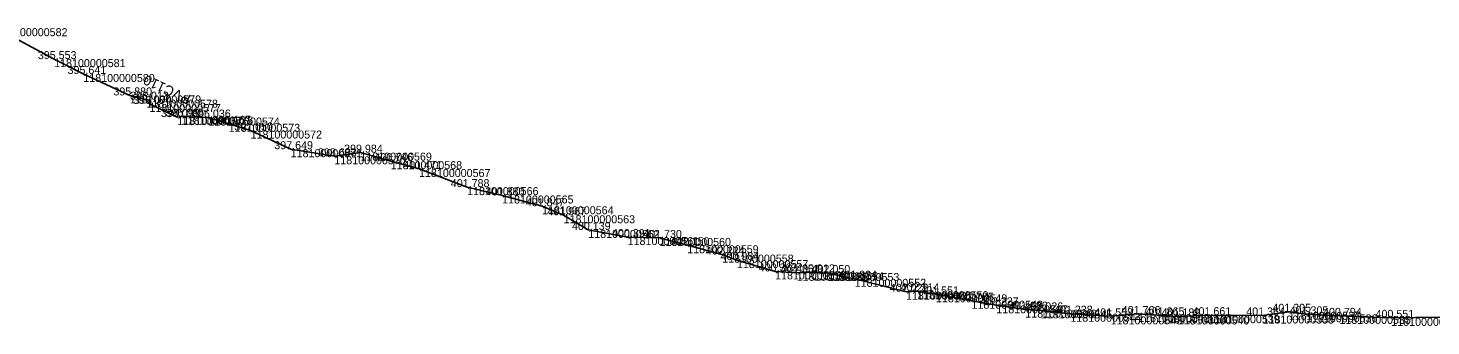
# Model space of a CAD drawing. Extents: x -727171 to -722443, y -945718 to -941834.
# Drawn here: x -723699.8 to -723489.4, y -945345 to -945300.3 of the extents above; entities that cross this region are included whole.
import ezdxf

# ---------------------------------------------------------------- set-up
doc = ezdxf.new("R2010")
doc.units = 0
for name, color, linetype in [('Vrstva 28', 7, 'Continuous'), ('Vrstva 31', 7, 'Continuous'), ('Vrstva 33', 7, 'Continuous'), ('Vrstva 35', 7, 'Continuous'), ('Vrstva 60', 7, 'Continuous'), ('Vrstva 61', 7, 'Continuous')]:
    doc.layers.add(name, color=color, linetype=linetype)

msp = doc.modelspace()

# ---------------------------------------------------------------- linework, layer by layer
at = {"layer": 'Vrstva 28'}
msp.add_lwpolyline([(-723484.45, -945343.68), (-723495.39, -945343.82), (-723503.17, -945343.52), (-723508.17, -945343.29), (-723510.76, -945342.91), (-723514.69, -945343.46), (-723522.83, -945343.42), (-723527.38, -945343.61), (-723529.76, -945343.45), (-723533.35, -945343.24), (-723537.47, -945343.59), (-723543.52, -945343.2), (-723547.95, -945342.7), (-723550.28, -945342.59), (-723554.62, -945341.94), (-723558.35, -945341.25), (-723563.68, -945340.29), (-723566.51, -945339.82), (-723568.16, -945339.9), (-723575.86, -945337.96), (-723579.88, -945337.1), (-723582.19, -945336.99), (-723584.56, -945337.06), (-723587.8, -945336.85), (-723593.53, -945335.15), (-723595.73, -945334.33), (-723600.98, -945332.93), (-723605.13, -945331.83), (-723609.91, -945331.7), (-723615.82, -945330.63), (-723619.51, -945328.43), (-723622.74, -945327.08), (-723628.74, -945325.46), (-723633.99, -945324.21), (-723641.2, -945321.48), (-723645.45, -945320.32), (-723649.99, -945319.03), (-723653.9, -945319.58), (-723660.45, -945318.52), (-723666.46, -945315.72), (-723669.74, -945314.71), (-723672.79, -945313.77), (-723676.78, -945313.62), (-723677.46, -945313.7), (-723681.63, -945311.73), (-723682.08, -945311.09), (-723684.59, -945310.45), (-723691.55, -945307.23), (-723695.92, -945305), (-723704.63, -945300.36)], dxfattribs=at)
at = {"layer": 'Vrstva 31'}
msp.add_lwpolyline([(-723484.45, -945343.68), (-723495.39, -945343.82), (-723503.17, -945343.52), (-723508.17, -945343.29), (-723510.76, -945342.91), (-723514.69, -945343.46), (-723522.83, -945343.42), (-723527.38, -945343.61), (-723529.76, -945343.45), (-723533.35, -945343.24), (-723537.47, -945343.59), (-723543.52, -945343.2), (-723547.95, -945342.7), (-723550.28, -945342.59), (-723554.62, -945341.94), (-723558.35, -945341.25), (-723563.68, -945340.29), (-723566.51, -945339.82), (-723568.16, -945339.9), (-723575.86, -945337.96), (-723579.88, -945337.1), (-723582.19, -945336.99), (-723584.56, -945337.06), (-723587.8, -945336.85), (-723593.53, -945335.15), (-723595.73, -945334.33), (-723600.98, -945332.93), (-723605.13, -945331.83), (-723609.91, -945331.7), (-723615.82, -945330.63), (-723619.51, -945328.43), (-723622.74, -945327.08), (-723628.74, -945325.46), (-723633.99, -945324.21), (-723641.2, -945321.48), (-723645.45, -945320.32), (-723649.99, -945319.03), (-723653.9, -945319.58), (-723660.45, -945318.52), (-723666.46, -945315.72), (-723669.74, -945314.71), (-723672.79, -945313.77), (-723676.78, -945313.62), (-723677.46, -945313.7), (-723681.63, -945311.73), (-723682.08, -945311.09), (-723684.59, -945310.45), (-723691.55, -945307.23), (-723695.92, -945305), (-723704.63, -945300.36)], dxfattribs=at)
at = {"layer": 'Vrstva 33'}
msp.add_lwpolyline([(-723484.45, -945343.68), (-723495.39, -945343.82), (-723503.17, -945343.52), (-723508.17, -945343.29), (-723510.76, -945342.91), (-723514.69, -945343.46), (-723522.83, -945343.42), (-723527.38, -945343.61), (-723529.76, -945343.45), (-723533.35, -945343.24), (-723537.47, -945343.59), (-723543.52, -945343.2), (-723547.95, -945342.7), (-723550.28, -945342.59), (-723554.62, -945341.94), (-723558.35, -945341.25), (-723563.68, -945340.29), (-723566.51, -945339.82), (-723568.16, -945339.9), (-723575.86, -945337.96), (-723579.88, -945337.1), (-723582.19, -945336.99), (-723584.56, -945337.06), (-723587.8, -945336.85), (-723593.53, -945335.15), (-723595.73, -945334.33), (-723600.98, -945332.93), (-723605.13, -945331.83), (-723609.91, -945331.7), (-723615.82, -945330.63), (-723619.51, -945328.43), (-723622.74, -945327.08), (-723628.74, -945325.46), (-723633.99, -945324.21), (-723641.2, -945321.48), (-723645.45, -945320.32), (-723649.99, -945319.03), (-723653.9, -945319.58), (-723660.45, -945318.52), (-723666.46, -945315.72), (-723669.74, -945314.71), (-723672.79, -945313.77), (-723676.78, -945313.62), (-723677.46, -945313.7), (-723681.63, -945311.73), (-723682.08, -945311.09), (-723684.59, -945310.45), (-723691.55, -945307.23), (-723695.92, -945305), (-723704.63, -945300.36)], dxfattribs=at)
at = {"layer": 'Vrstva 35'}
msp.add_lwpolyline([(-723676.78, -945313.62), (-723677.46, -945313.7), (-723681.63, -945311.73), (-723682.08, -945311.09)], dxfattribs=at)
at = {"layer": 'Vrstva 60'}
for p, q in [((-723695.92, -945305), (-723695.92, -945305)), ((-723691.55, -945307.23), (-723691.55, -945307.23)), ((-723684.59, -945310.45), (-723684.59, -945310.45)), ((-723682.08, -945311.09), (-723682.08, -945311.09)), ((-723681.63, -945311.73), (-723681.63, -945311.73)), ((-723677.46, -945313.7), (-723677.46, -945313.7)), ((-723676.78, -945313.62), (-723676.78, -945313.62)), ((-723672.79, -945313.77), (-723672.79, -945313.77)), ((-723669.74, -945314.71), (-723669.74, -945314.71)), ((-723666.46, -945315.72), (-723666.46, -945315.72)), ((-723660.45, -945318.52), (-723660.45, -945318.52)), ((-723653.9, -945319.58), (-723653.9, -945319.58)), ((-723649.99, -945319.03), (-723649.99, -945319.03)), ((-723645.45, -945320.32), (-723645.45, -945320.32)), ((-723641.2, -945321.48), (-723641.2, -945321.48)), ((-723633.99, -945324.21), (-723633.99, -945324.21)), ((-723628.74, -945325.46), (-723628.74, -945325.46)), ((-723622.74, -945327.08), (-723622.74, -945327.08)), ((-723619.51, -945328.43), (-723619.51, -945328.43)), ((-723615.82, -945330.63), (-723615.82, -945330.63)), ((-723609.91, -945331.7), (-723609.91, -945331.7)), ((-723605.13, -945331.83), (-723605.13, -945331.83)), ((-723600.98, -945332.93), (-723600.98, -945332.93)), ((-723595.73, -945334.33), (-723595.73, -945334.33)), ((-723593.53, -945335.15), (-723593.53, -945335.15)), ((-723587.8, -945336.85), (-723587.8, -945336.85)), ((-723582.19, -945336.99), (-723582.19, -945336.99)), ((-723584.56, -945337.06), (-723584.56, -945337.06)), ((-723579.88, -945337.1), (-723579.88, -945337.1)), ((-723575.86, -945337.96), (-723575.86, -945337.96)), ((-723568.16, -945339.9), (-723568.16, -945339.9)), ((-723566.51, -945339.82), (-723566.51, -945339.82)), ((-723563.68, -945340.29), (-723563.68, -945340.29)), ((-723558.35, -945341.25), (-723558.35, -945341.25)), ((-723554.62, -945341.94), (-723554.62, -945341.94)), ((-723550.28, -945342.59), (-723550.28, -945342.59)), ((-723547.95, -945342.7), (-723547.95, -945342.7)), ((-723543.52, -945343.2), (-723543.52, -945343.2)), ((-723533.35, -945343.24), (-723533.35, -945343.24)), ((-723510.76, -945342.91), (-723510.76, -945342.91)), ((-723508.17, -945343.29), (-723508.17, -945343.29)), ((-723537.47, -945343.59), (-723537.47, -945343.59)), ((-723529.76, -945343.45), (-723529.76, -945343.45)), ((-723527.38, -945343.61), (-723527.38, -945343.61)), ((-723522.83, -945343.42), (-723522.83, -945343.42)), ((-723514.69, -945343.46), (-723514.69, -945343.46)), ((-723503.17, -945343.52), (-723503.17, -945343.52)), ((-723495.39, -945343.82), (-723495.39, -945343.82))]:
    msp.add_line(p, q, dxfattribs=at)

# ---------------------------------------------------------------- texts
at = {"layer": 'Vrstva 35'}
msp.add_text('PVC110', height=1.5, rotation=154.8068, dxfattribs=at).set_placement((-723675.31, -945310.49))
at = {"layer": 'Vrstva 60'}
for s, p in [('118100000582', (-723704.63, -945301.56)), ('118100000581', (-723695.92, -945306.2)), ('118100000580', (-723691.55, -945308.43)), ('118100000579', (-723684.59, -945311.65)), ('118100000578', (-723682.08, -945312.29)), ('118100000577', (-723681.63, -945312.93)), ('118100000576', (-723677.46, -945314.9)), ('118100000575', (-723676.78, -945314.82)), ('118100000574', (-723672.79, -945314.97)), ('118100000573', (-723669.74, -945315.91)), ('118100000572', (-723666.46, -945316.92)), ('118100000571', (-723660.45, -945319.72)), ('118100000570', (-723653.9, -945320.78)), ('118100000569', (-723649.99, -945320.23)), ('118100000568', (-723645.45, -945321.52)), ('118100000567', (-723641.2, -945322.69)), ('118100000566', (-723633.99, -945325.41)), ('118100000565', (-723628.74, -945326.66)), ('118100000564', (-723622.74, -945328.28)), ('118100000563', (-723619.51, -945329.63)), ('118100000562', (-723615.82, -945331.83)), ('118100000561', (-723609.91, -945332.9)), ('118100000560', (-723605.13, -945333.03)), ('118100000559', (-723600.98, -945334.13)), ('118100000558', (-723595.73, -945335.53)), ('118100000557', (-723593.53, -945336.35)), ('118100000556', (-723587.8, -945338.05)), ('118100000555', (-723584.56, -945338.26)), ('118100000554', (-723582.19, -945338.19)), ('118100000553', (-723579.88, -945338.3)), ('118100000552', (-723575.86, -945339.16)), ('118100000551', (-723568.16, -945341.1)), ('118100000550', (-723566.51, -945341.02)), ('118100000549', (-723563.68, -945341.49)), ('118100000548', (-723558.35, -945342.45)), ('118100000547', (-723554.62, -945343.14)), ('118100000546', (-723550.28, -945343.79)), ('118100000545', (-723547.95, -945343.9)), ('118100000544', (-723543.52, -945344.4)), ('118100000542', (-723533.35, -945344.44)), ('118100000537', (-723510.76, -945344.11)), ('118100000536', (-723508.17, -945344.49)), ('118100000543', (-723537.47, -945344.8)), ('118100000541', (-723529.76, -945344.65)), ('118100000540', (-723527.38, -945344.81)), ('118100000539', (-723522.83, -945344.62)), ('118100000538', (-723514.69, -945344.67)), ('118100000535', (-723503.17, -945344.72)), ('118100000534', (-723495.39, -945345.02))]:
    msp.add_text(s, height=1.2, dxfattribs=at).set_placement(p)
at = {"layer": 'Vrstva 61'}
for s, p in [('395.553', (-723698.37, -945305)), ('395.641', (-723693.91, -945307.23)), ('395.880', (-723687.04, -945310.45)), ('396.013', (-723684.53, -945311.09)), ('396.074', (-723684.08, -945311.73)), ('396.093', (-723679.91, -945313.7)), ('396.065', (-723679.23, -945313.62)), ('396.036', (-723675.24, -945313.77)), ('396.167', (-723672.2, -945314.71)), ('397.050', (-723668.91, -945315.72)), ('397.649', (-723662.91, -945318.52)), ('399.984', (-723652.44, -945319.03)), ('398.603', (-723656.35, -945319.58)), ('400.746', (-723647.9, -945320.32)), ('401.471', (-723643.56, -945321.48)), ('401.788', (-723636.44, -945324.21)), ('401.880', (-723631.19, -945325.46)), ('401.847', (-723625.19, -945327.08)), ('401.967', (-723621.96, -945328.43)), ('400.139', (-723618.27, -945330.63)), ('400.391', (-723612.26, -945331.7)), ('401.730', (-723607.58, -945331.83)), ('402.150', (-723603.43, -945332.93)), ('402.224', (-723598.18, -945334.33)), ('400.984', (-723595.98, -945335.15)), ('400.362', (-723590.25, -945336.85)), ('401.351', (-723586.92, -945337.06)), ('400.912', (-723584.64, -945336.99)), ('402.050', (-723582.33, -945337.1)), ('401.824', (-723578.31, -945337.96)), ('402.022', (-723570.61, -945339.9)), ('402.114', (-723568.96, -945339.82)), ('401.551', (-723566.03, -945340.29)), ('401.785', (-723560.81, -945341.25)), ('402.227', (-723557.08, -945341.94)), ('401.686', (-723552.73, -945342.59)), ('402.026', (-723550.4, -945342.7)), ('401.238', (-723545.97, -945343.2)), ('401.553', (-723539.92, -945343.59)), ('401.766', (-723535.81, -945343.24)), ('401.865', (-723532.21, -945343.45)), ('401.189', (-723529.84, -945343.61)), ('401.661', (-723525.19, -945343.42)), ('401.364', (-723517.14, -945343.46)), ('401.305', (-723513.22, -945342.91)), ('401.305', (-723510.63, -945343.29)), ('400.794', (-723505.62, -945343.52)), ('400.551', (-723497.75, -945343.82))]:
    msp.add_text(s, height=1.2, dxfattribs=at).set_placement(p)

doc.saveas('drawing.dxf')
